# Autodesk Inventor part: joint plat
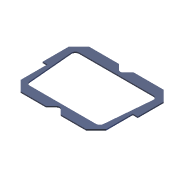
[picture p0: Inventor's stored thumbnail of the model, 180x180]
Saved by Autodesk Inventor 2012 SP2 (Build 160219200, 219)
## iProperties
Created: 2013-04
Part Number: joint plat
Material: Default
Document SubType Name: Modeling
Designer: papa
Density: 1 g/cm^3
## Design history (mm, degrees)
node "joint plat1"
node "joint plat"
node "Base1"
